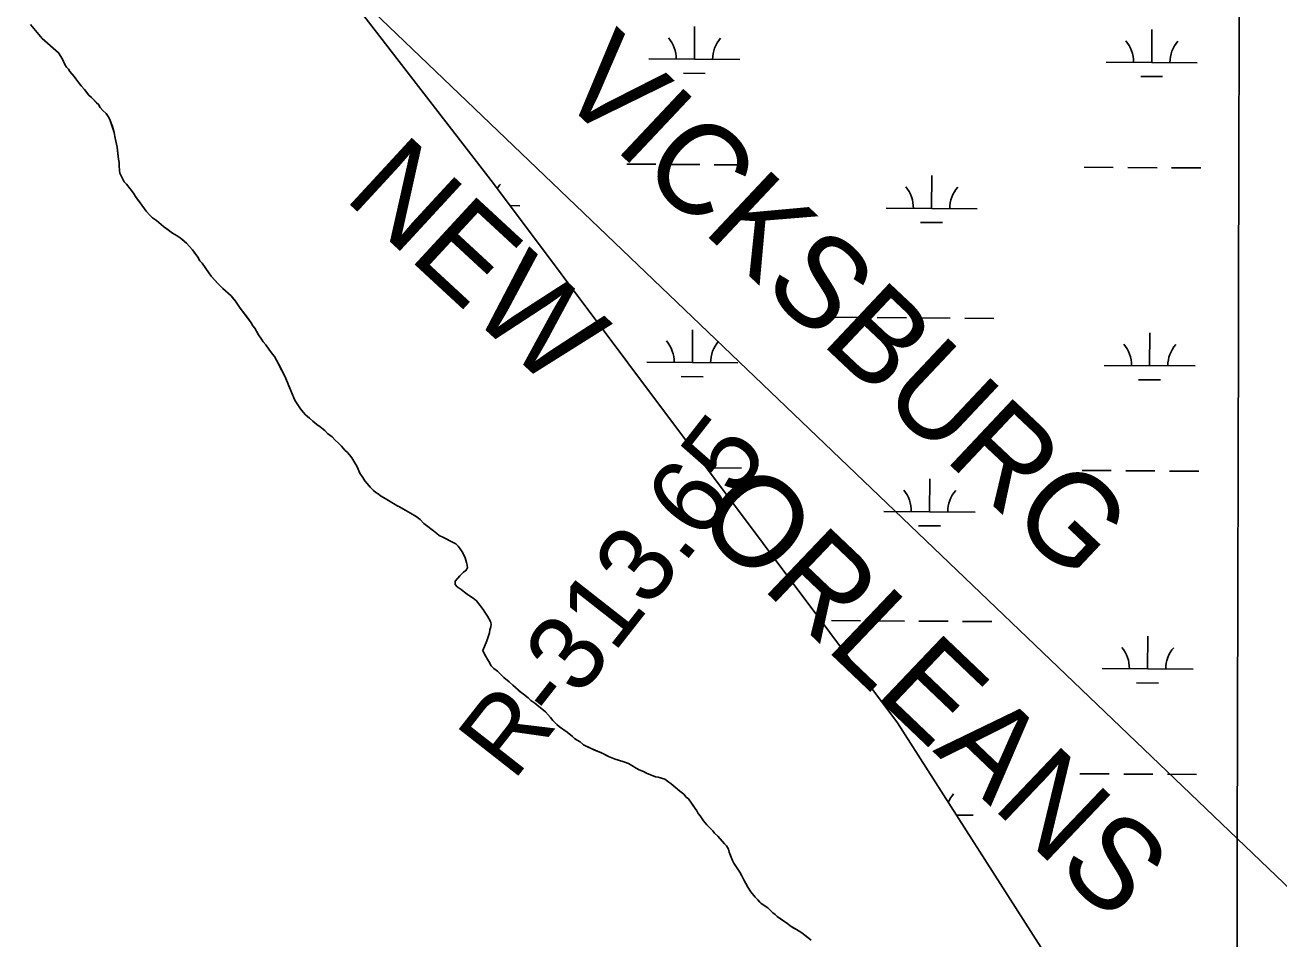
# Model space of a CAD drawing. Extents: x 3172231 to 3210228, y 940198 to 965780.
# Drawn here: x 3196029 to 3197406, y 947239 to 948241 of the extents above; entities that cross this region are included whole.
import ezdxf

# ---------------------------------------------------------------- set-up
doc = ezdxf.new("R2010")
doc.units = 0
for name, color, linetype in [('V-GRID-MAJR', 7, 'Continuous'), ('V-RIVR-RANG-IDEN', 7, 'Continuous'), ('V-SITE-VEGE', 7, 'Continuous'), ('V-TOPO-BNDY', 7, 'Continuous'), ('V-TOPO-GNAM-IDEN', 7, 'Continuous'), ('V-TOPO-SHOR', 7, 'Continuous'), ('V-WETL-SWMP', 7, 'Continuous')]:
    doc.layers.add(name, color=color, linetype=linetype)

msp = doc.modelspace()

# ---------------------------------------------------------------- linework, layer by layer
at = {"layer": 'V-GRID-MAJR'}
msp.add_spline([(3197355.974, 945678.243), (3197370.077, 951738.379), (3197384.187, 957801.599), (3197398.298, 963864.87), (3197398.305, 963867.904)], degree=3, dxfattribs=at)
at = {"layer": 'V-SITE-VEGE'}
for p, q in [((3196035.421, 948241.825), (3196048.367, 948226.26)), ((3196048.367, 948226.26), (3196066.192, 948210.847)), ((3196066.192, 948210.847), (3196070.723, 948203.693)), ((3196070.723, 948203.693), (3196073.135, 948198.035)), ((3196073.135, 948198.035), (3196074.859, 948195.028)), ((3196074.859, 948195.028), (3196077.014, 948192.884)), ((3196077.014, 948192.884), (3196078.736, 948190.31)), ((3196078.736, 948190.31), (3196083.475, 948184.731)), ((3196083.475, 948184.731), (3196085.2, 948182.155)), ((3196085.2, 948182.155), (3196088.645, 948177.862)), ((3196088.645, 948177.862), (3196091.229, 948174.43)), ((3196091.229, 948174.43), (3196094.676, 948170.567)), ((3196094.676, 948170.567), (3196099.415, 948164.13)), ((3196099.415, 948164.13), (3196102.428, 948161.558)), ((3196102.428, 948161.558), (3196110.177, 948153.835)), ((3196110.177, 948153.835), (3196111.904, 948150.83)), ((3196111.904, 948150.83), (3196114.916, 948147.398)), ((3196114.916, 948147.398), (3196118.361, 948143.966)), ((3196118.361, 948143.966), (3196120.516, 948140.959)), ((3196120.516, 948140.959), (3196122.672, 948137.527)), ((3196122.672, 948137.527), (3196127.425, 948123.352)), ((3196127.425, 948123.352), (3196127.864, 948119.056)), ((3196127.864, 948119.056), (3196129.162, 948113.901)), ((3196129.162, 948113.901), (3196130.465, 948107.028)), ((3196130.465, 948107.028), (3196132.21, 948094.136)), ((3196132.21, 948094.136), (3196132.644, 948090.269)), ((3196132.644, 948090.269), (3196132.65, 948086.83)), ((3196132.65, 948086.83), (3196133.088, 948081.674)), ((3196133.088, 948081.674), (3196133.524, 948078.665)), ((3196133.524, 948078.665), (3196138.27, 948069.22)), ((3196138.27, 948069.22), (3196140.852, 948066.645)), ((3196140.852, 948066.645), (3196144.729, 948061.495)), ((3196144.729, 948061.495), (3196148.608, 948056.774)), ((3196148.608, 948056.774), (3196150.762, 948052.909)), ((3196150.762, 948052.909), (3196155.934, 948046.042)), ((3196155.934, 948046.042), (3196162.395, 948037.029)), ((3196162.395, 948037.029), (3196166.272, 948032.739)), ((3196166.272, 948032.739), (3196169.287, 948029.736)), ((3196169.287, 948029.736), (3196173.589, 948026.736)), ((3196173.589, 948026.736), (3196181.337, 948020.303)), ((3196181.337, 948020.303), (3196191.235, 948013.014)), ((3196191.235, 948013.014), (3196196.398, 948010.014)), ((3196196.398, 948010.014), (3196199.843, 948007.872)), ((3196199.843, 948007.872), (3196206.728, 948001.869)), ((3196206.728, 948001.869), (3196213.19, 947994.572)), ((3196213.19, 947994.572), (3196219.221, 947986.419)), ((3196219.221, 947986.419), (3196221.377, 947982.554)), ((3196221.377, 947982.554), (3196223.96, 947979.98)), ((3196223.96, 947979.98), (3196231.286, 947969.251)), ((3196231.286, 947969.251), (3196233.87, 947965.816)), ((3196233.87, 947965.816), (3196241.194, 947957.663)), ((3196241.194, 947957.663), (3196243.776, 947955.089)), ((3196243.776, 947955.089), (3196246.359, 947952.086)), ((3196246.359, 947952.086), (3196255.831, 947943.939)), ((3196255.831, 947943.939), (3196260.568, 947938.359)), ((3196260.568, 947938.359), (3196265.739, 947930.634)), ((3196265.739, 947930.634), (3196277.804, 947914.323)), ((3196277.804, 947914.323), (3196279.528, 947911.319)), ((3196279.528, 947911.319), (3196281.683, 947908.743)), ((3196281.683, 947908.743), (3196283.407, 947905.308)), ((3196283.407, 947905.308), (3196285.564, 947901.445)), ((3196285.564, 947901.445), (3196289.011, 947896.723)), ((3196289.011, 947896.723), (3196290.735, 947893.716)), ((3196290.735, 947893.716), (3196293.75, 947890.284)), ((3196293.75, 947890.284), (3196297.196, 947885.563)), ((3196297.196, 947885.563), (3196301.075, 947879.982)), ((3196301.075, 947879.982), (3196303.23, 947877.41)), ((3196303.23, 947877.41), (3196307.541, 947869.681)), ((3196307.541, 947869.681), (3196313.578, 947858.087)), ((3196313.578, 947858.087), (3196315.737, 947853.363)), ((3196315.737, 947853.363), (3196320.916, 947840.907)), ((3196320.916, 947840.907), (3196324.373, 947832.321)), ((3196324.373, 947832.321), (3196326.098, 947828.885)), ((3196326.098, 947828.885), (3196328.682, 947824.592)), ((3196328.682, 947824.592), (3196331.699, 947820.3)), ((3196331.699, 947820.3), (3196334.716, 947816.437)), ((3196334.716, 947816.437), (3196337.298, 947813.433)), ((3196337.298, 947813.433), (3196341.603, 947810.002)), ((3196341.603, 947810.002), (3196345.478, 947806.572)), ((3196345.478, 947806.572), (3196349.783, 947803.141)), ((3196349.783, 947803.141), (3196353.226, 947800.569)), ((3196353.226, 947800.569), (3196358.391, 947796.281)), ((3196358.391, 947796.281), (3196361.403, 947793.276)), ((3196361.403, 947793.276), (3196366.566, 947789.42)), ((3196366.566, 947789.42), (3196369.583, 947785.985)), ((3196369.583, 947785.985), (3196373.888, 947782.127)), ((3196373.888, 947782.127), (3196376.903, 947779.123)), ((3196376.903, 947779.123), (3196380.349, 947774.832)), ((3196380.349, 947774.832), (3196383.362, 947772.258)), ((3196383.362, 947772.258), (3196385.514, 947769.683)), ((3196385.514, 947769.683), (3196388.097, 947766.251)), ((3196388.097, 947766.251), (3196393.702, 947757.236)), ((3196393.702, 947757.236), (3196396.727, 947749.504)), ((3196396.727, 947749.504), (3196400.174, 947744.784)), ((3196400.174, 947744.784), (3196402.329, 947741.349)), ((3196402.329, 947741.349), (3196404.913, 947738.345)), ((3196404.913, 947738.345), (3196408.36, 947734.052)), ((3196408.36, 947734.052), (3196411.807, 947730.622)), ((3196411.807, 947730.622), (3196414.387, 947728.478)), ((3196414.387, 947728.478), (3196416.97, 947726.763)), ((3196416.97, 947726.763), (3196419.55, 947724.619)), ((3196419.55, 947724.619), (3196422.993, 947722.909)), ((3196422.993, 947722.909), (3196433.749, 947716.478)), ((3196433.749, 947716.478), (3196438.482, 947713.478)), ((3196438.482, 947713.478), (3196438.914, 947713.48)), ((3196438.914, 947713.48), (3196447.516, 947708.768)), ((3196447.516, 947708.768), (3196452.679, 947705.769)), ((3196452.679, 947705.769), (3196458.704, 947701.913)), ((3196458.704, 947701.913), (3196463.009, 947698.911)), ((3196463.009, 947698.911), (3196467.314, 947694.192)), ((3196467.314, 947694.192), (3196469.894, 947692.048)), ((3196469.894, 947692.048), (3196477.642, 947686.475)), ((3196477.642, 947686.475), (3196481.516, 947683.473)), ((3196481.516, 947683.473), (3196484.097, 947681.328)), ((3196484.097, 947681.328), (3196488.83, 947679.188)), ((3196488.83, 947679.188), (3196492.273, 947677.046)), ((3196492.273, 947677.046), (3196495.713, 947675.334)), ((3196495.713, 947675.334), (3196502.166, 947671.908)), ((3196502.166, 947671.908), (3196504.749, 947669.333)), ((3196504.749, 947669.333), (3196506.901, 947666.759)), ((3196506.901, 947666.759), (3196509.92, 947662.036)), ((3196509.92, 947662.036), (3196512.511, 947656.884)), ((3196512.511, 947656.884), (3196513.807, 947651.729)), ((3196513.807, 947651.729), (3196514.674, 947648.722)), ((3196514.674, 947648.722), (3196515.108, 947645.714)), ((3196506.529, 947637.102), (3196501.382, 947631.077)), ((3196510.819, 947640.979), (3196506.529, 947637.102)), ((3196513.396, 947642.701), (3196510.819, 947640.979)), ((3196515.108, 947645.714), (3196513.396, 947642.701)), ((3196501.382, 947631.077), (3196501.388, 947627.638)), ((3196501.388, 947627.638), (3196503.543, 947625.064)), ((3196503.543, 947625.064), (3196508.274, 947622.063)), ((3196508.274, 947622.063), (3196511.718, 947619.061)), ((3196511.718, 947619.061), (3196516.023, 947615.631)), ((3196516.023, 947615.631), (3196521.188, 947612.632)), ((3196521.188, 947612.632), (3196525.059, 947609.63)), ((3196525.059, 947609.63), (3196532.383, 947600.189)), ((3196532.383, 947600.189), (3196534.107, 947597.182)), ((3196534.107, 947597.182), (3196537.124, 947592.892)), ((3196537.124, 947592.892), (3196540.145, 947586.879)), ((3196539.731, 947577.853), (3196539.307, 947574.415)), ((3196540.585, 947580.864), (3196539.731, 947577.853)), ((3196540.145, 947586.879), (3196541.009, 947583.872)), ((3196541.009, 947583.872), (3196540.585, 947580.864)), ((3196536.315, 947565.811), (3196532.037, 947555.061)), ((3196539.307, 947574.415), (3196536.315, 947565.811)), ((3196532.037, 947555.061), (3196533.761, 947551.197)), ((3196533.761, 947551.197), (3196538.504, 947543.037)), ((3196538.504, 947543.037), (3196541.093, 947538.317)), ((3196541.093, 947538.317), (3196544.105, 947535.312)), ((3196544.105, 947535.312), (3196547.98, 947532.312)), ((3196547.98, 947532.312), (3196554.87, 947525.447)), ((3196554.87, 947525.447), (3196560.895, 947520.73)), ((3196560.895, 947520.73), (3196564.77, 947516.87)), ((3196564.77, 947516.87), (3196573.81, 947509.149)), ((3196573.81, 947509.149), (3196576.392, 947507.009)), ((3196576.392, 947507.009), (3196581.557, 947503.148)), ((3196581.557, 947503.148), (3196584.572, 947500.144)), ((3196584.572, 947500.144), (3196588.875, 947497.144)), ((3196588.875, 947497.144), (3196593.178, 947493.713)), ((3196593.178, 947493.713), (3196596.62, 947491.141)), ((3196596.62, 947491.141), (3196600.495, 947487.711)), ((3196600.495, 947487.711), (3196606.094, 947481.704)), ((3196606.094, 947481.704), (3196608.679, 947478.269)), ((3196608.679, 947478.269), (3196612.984, 947473.981)), ((3196612.984, 947473.981), (3196615.998, 947471.406)), ((3196615.998, 947471.406), (3196624.606, 947465.406)), ((3196624.606, 947465.406), (3196630.199, 947460.687)), ((3196630.199, 947460.687), (3196632.354, 947458.543)), ((3196632.354, 947458.543), (3196635.364, 947456.831)), ((3196635.364, 947456.831), (3196638.807, 947454.687)), ((3196638.807, 947454.687), (3196642.252, 947451.684)), ((3196642.252, 947451.684), (3196650.853, 947447.404)), ((3196650.853, 947447.404), (3196662.037, 947442.696)), ((3196662.037, 947442.696), (3196669.781, 947438.841)), ((3196669.781, 947438.841), (3196677.092, 947435.847)), ((3196677.092, 947435.847), (3196685.694, 947433.285)), ((3196685.694, 947433.285), (3196691.713, 947431.147)), ((3196691.713, 947431.147), (3196695.586, 947429.005)), ((3196695.586, 947429.005), (3196700.321, 947426.004)), ((3196700.321, 947426.004), (3196703.329, 947424.29)), ((3196703.329, 947424.29), (3196708.062, 947422.15)), ((3196708.062, 947422.15), (3196711.501, 947420.436)), ((3196711.501, 947420.436), (3196721.395, 947416.588)), ((3196721.395, 947416.588), (3196724.405, 947416.164)), ((3196724.405, 947416.164), (3196731.715, 947414.028)), ((3196731.715, 947414.028), (3196734.727, 947411.885)), ((3196734.727, 947411.885), (3196738.602, 947408.883)), ((3196738.602, 947408.883), (3196748.072, 947400.734)), ((3196748.072, 947400.734), (3196752.375, 947397.306)), ((3196752.375, 947397.306), (3196754.959, 947394.301)), ((3196754.959, 947394.301), (3196757.542, 947392.157)), ((3196757.542, 947392.157), (3196764.868, 947381.856)), ((3196764.868, 947381.856), (3196766.592, 947379.279)), ((3196766.592, 947379.279), (3196768.316, 947376.275)), ((3196768.316, 947376.275), (3196770.471, 947373.7)), ((3196770.471, 947373.7), (3196773.918, 947368.12)), ((3196773.918, 947368.12), (3196777.795, 947363.827)), ((3196777.795, 947363.827), (3196784.254, 947357.392)), ((3196784.254, 947357.392), (3196785.976, 947354.818)), ((3196785.976, 947354.818), (3196789.851, 947351.385)), ((3196789.851, 947351.385), (3196797.173, 947342.804)), ((3196797.173, 947342.804), (3196799.325, 947340.658)), ((3196799.325, 947340.658), (3196801.482, 947337.226)), ((3196801.482, 947337.226), (3196802.348, 947333.787)), ((3196802.348, 947333.787), (3196805.803, 947324.77)), ((3196805.803, 947324.77), (3196807.523, 947321.763)), ((3196807.523, 947321.763), (3196810.974, 947316.182)), ((3196810.974, 947316.182), (3196813.991, 947311.89)), ((3196813.991, 947311.89), (3196816.147, 947308.027)), ((3196816.147, 947308.027), (3196818.306, 947303.305)), ((3196818.306, 947303.305), (3196822.617, 947295.575)), ((3196822.617, 947295.575), (3196826.066, 947290.425)), ((3196826.066, 947290.425), (3196830.803, 947284.416)), ((3196830.803, 947284.416), (3196833.818, 947281.411)), ((3196833.818, 947281.411), (3196835.97, 947278.837)), ((3196835.97, 947278.837), (3196836.832, 947277.979)), ((3196836.832, 947277.979), (3196844.578, 947272.836)), ((3196844.578, 947272.836), (3196850.175, 947267.26)), ((3196850.175, 947267.26), (3196852.757, 947265.546)), ((3196852.757, 947265.546), (3196854.908, 947263.399)), ((3196854.908, 947263.399), (3196866.528, 947255.256)), ((3196866.528, 947255.256), (3196869.113, 947253.11)), ((3196869.113, 947253.11), (3196875.996, 947248.826)), ((3196875.996, 947248.826), (3196882.019, 947245.399)), ((3196882.019, 947245.399), (3196892.349, 947237.252))]:
    msp.add_line(p, q, dxfattribs=at)
at = {"layer": 'V-TOPO-BNDY'}
msp.add_line((3194332.024, 950245.511), (3197716.878, 947007.215), dxfattribs=at)
at = {"layer": 'V-TOPO-SHOR'}
for points in [[(3196070.723, 948203.693), (3196066.192, 948210.847), (3196048.367, 948226.26), (3196035.421, 948241.825)], [(3196169.287, 948029.736), (3196166.272, 948032.739), (3196162.395, 948037.029), (3196155.934, 948046.042), (3196153.347, 948049.477), (3196150.762, 948052.909), (3196148.608, 948056.774), (3196144.729, 948061.495), (3196140.852, 948066.645), (3196138.27, 948069.22), (3196136.543, 948072.654), (3196133.524, 948078.665), (3196133.088, 948081.674), (3196132.65, 948086.83), (3196132.644, 948090.267), (3196132.208, 948094.136), (3196131.335, 948100.151), (3196130.465, 948107.026), (3196129.162, 948113.901), (3196127.864, 948119.056), (3196127.425, 948123.352), (3196125.265, 948129.795), (3196123.968, 948133.66), (3196122.672, 948137.527), (3196120.516, 948140.959), (3196118.361, 948143.966), (3196114.916, 948147.398), (3196111.904, 948150.83), (3196110.177, 948153.835), (3196108.025, 948155.979), (3196102.428, 948161.558), (3196099.415, 948164.13), (3196097.26, 948167.135), (3196094.676, 948170.567), (3196091.229, 948174.43), (3196088.645, 948177.862), (3196085.2, 948182.155), (3196083.475, 948184.731), (3196081.321, 948187.305), (3196078.736, 948190.31), (3196077.014, 948192.884), (3196074.859, 948195.028), (3196073.135, 948198.035), (3196070.723, 948203.693)], [(3196513.807, 947651.729), (3196512.509, 947656.884), (3196509.92, 947662.036), (3196506.904, 947666.759), (3196504.749, 947669.333), (3196502.166, 947671.908), (3196495.713, 947675.334), (3196492.273, 947677.046), (3196488.83, 947679.188), (3196484.097, 947681.328), (3196481.516, 947683.473), (3196477.642, 947686.475), (3196469.896, 947692.048), (3196467.314, 947694.192), (3196463.007, 947698.911), (3196458.704, 947701.913), (3196452.679, 947705.769), (3196447.516, 947708.768), (3196443.645, 947710.91), (3196438.912, 947713.48), (3196438.482, 947713.478), (3196433.749, 947716.478), (3196422.993, 947722.907), (3196419.55, 947724.619), (3196416.97, 947726.763), (3196414.387, 947728.478), (3196411.805, 947730.622), (3196408.36, 947734.052), (3196404.913, 947738.345), (3196402.329, 947741.349), (3196400.174, 947744.784), (3196396.727, 947749.504), (3196395.001, 947753.799), (3196393.704, 947757.236), (3196390.256, 947762.816), (3196388.099, 947766.251), (3196385.514, 947769.683), (3196383.362, 947772.258), (3196380.349, 947774.832), (3196376.903, 947779.123), (3196373.888, 947782.127), (3196369.583, 947785.985), (3196366.568, 947789.42), (3196361.403, 947793.276), (3196358.391, 947796.281), (3196353.226, 947800.569), (3196349.783, 947803.141), (3196345.478, 947806.572), (3196341.603, 947810.002), (3196337.298, 947813.433), (3196334.716, 947816.437), (3196331.699, 947820.3), (3196328.682, 947824.592), (3196326.098, 947828.885), (3196324.371, 947832.319), (3196320.916, 947840.909), (3196318.76, 947846.063), (3196317.464, 947849.07), (3196315.737, 947853.363), (3196313.578, 947858.087), (3196309.265, 947866.244), (3196307.541, 947869.681), (3196305.384, 947873.544), (3196303.23, 947877.408), (3196301.075, 947879.982), (3196298.921, 947882.989), (3196297.196, 947885.563), (3196293.75, 947890.284), (3196290.735, 947893.716), (3196289.011, 947896.723), (3196285.564, 947901.443), (3196283.407, 947905.308), (3196281.683, 947908.743), (3196279.528, 947911.319), (3196277.804, 947914.323), (3196273.065, 947920.76), (3196265.739, 947930.634), (3196260.568, 947938.359), (3196257.983, 947941.363), (3196255.831, 947943.937), (3196246.359, 947952.086), (3196243.776, 947955.091), (3196241.194, 947957.663), (3196238.177, 947961.098), (3196233.87, 947965.816), (3196231.286, 947969.251), (3196223.96, 947979.98), (3196221.377, 947982.554), (3196219.221, 947986.419), (3196217.066, 947989.423), (3196213.19, 947994.574), (3196206.728, 948001.869), (3196203.285, 948004.872), (3196199.841, 948007.874), (3196196.398, 948010.014), (3196191.235, 948013.014), (3196186.502, 948016.445), (3196181.337, 948020.303), (3196178.755, 948022.447), (3196173.589, 948026.736), (3196169.287, 948029.736)], [(3196816.147, 947308.027), (3196813.991, 947311.892), (3196810.974, 947316.182), (3196807.525, 947321.763), (3196805.803, 947324.77), (3196802.348, 947333.787), (3196801.482, 947337.226), (3196799.325, 947340.658), (3196797.173, 947342.804), (3196789.851, 947351.385), (3196785.976, 947354.818), (3196784.254, 947357.392), (3196780.807, 947360.825), (3196777.795, 947363.827), (3196773.918, 947368.12), (3196770.471, 947373.7), (3196768.316, 947376.275), (3196766.592, 947379.279), (3196764.868, 947381.856), (3196762.713, 947384.86), (3196757.542, 947392.157), (3196754.959, 947394.301), (3196752.375, 947397.306), (3196748.072, 947400.734), (3196745.057, 947403.308), (3196738.602, 947408.883), (3196734.727, 947411.885), (3196731.715, 947414.028), (3196724.405, 947416.164), (3196721.395, 947416.588), (3196711.503, 947420.438), (3196708.062, 947422.15), (3196703.329, 947424.29), (3196700.319, 947426.004), (3196695.586, 947429.005), (3196691.713, 947431.147), (3196685.694, 947433.285), (3196677.092, 947435.847), (3196669.781, 947438.841), (3196666.338, 947440.555), (3196662.037, 947442.696), (3196659.027, 947443.98), (3196653.866, 947446.12), (3196650.853, 947447.404), (3196647.413, 947449.116), (3196642.252, 947451.684), (3196638.807, 947454.687), (3196635.364, 947456.831), (3196632.354, 947458.543), (3196631.061, 947459.829), (3196630.199, 947460.687), (3196624.604, 947465.406), (3196615.998, 947471.406), (3196612.984, 947473.981), (3196608.679, 947478.269), (3196606.094, 947481.704), (3196600.495, 947487.711), (3196596.62, 947491.141), (3196593.178, 947493.713), (3196588.875, 947497.144), (3196584.572, 947500.144), (3196581.557, 947503.148), (3196576.392, 947507.007), (3196573.81, 947509.149), (3196570.797, 947511.723), (3196564.77, 947516.87), (3196560.895, 947520.73), (3196554.87, 947525.447), (3196552.285, 947528.021), (3196547.98, 947532.312), (3196544.105, 947535.312), (3196541.093, 947538.317), (3196538.504, 947543.037), (3196533.761, 947551.197), (3196532.037, 947555.061), (3196533.747, 947559.362), (3196536.315, 947565.813), (3196539.307, 947574.415), (3196539.731, 947577.853), (3196540.585, 947580.864), (3196541.009, 947583.872), (3196540.145, 947586.879), (3196537.124, 947592.892), (3196534.107, 947597.182), (3196532.383, 947600.189), (3196527.644, 947606.198), (3196525.059, 947609.63), (3196521.186, 947612.632), (3196516.023, 947615.631), (3196511.718, 947619.061), (3196508.276, 947622.063), (3196503.543, 947625.064), (3196501.388, 947627.638), (3196501.382, 947631.077), (3196504.384, 947634.519), (3196506.529, 947637.102), (3196510.819, 947640.979), (3196513.396, 947642.701), (3196515.108, 947645.714), (3196514.674, 947648.722), (3196513.807, 947651.729)], [(3196892.349, 947237.252), (3196888.475, 947240.253), (3196882.019, 947245.399), (3196875.996, 947248.826), (3196872.553, 947250.97), (3196869.113, 947253.11), (3196866.528, 947255.256), (3196862.225, 947258.257), (3196854.91, 947263.399), (3196852.757, 947265.546), (3196850.175, 947267.26), (3196847.16, 947270.262), (3196844.578, 947272.836), (3196840.705, 947275.409), (3196836.832, 947277.979), (3196835.97, 947278.837), (3196835.97, 947278.837), (3196833.818, 947281.411), (3196830.803, 947284.416), (3196826.066, 947290.425), (3196822.617, 947295.575), (3196818.306, 947303.303), (3196816.147, 947308.027)]]:
    msp.add_lwpolyline(points, dxfattribs=at)
at = {"layer": 'V-WETL-SWMP'}
for p, q in [((3196543.471, 948067.222), (3195915.087, 948880.76)), ((3196764.079, 948203.582), (3196764.324, 948239.581)), ((3197265.975, 948200.165), (3197266.22, 948236.164)), ((3196714.08, 948203.922), (3196814.078, 948203.241)), ((3197215.976, 948200.505), (3197315.974, 948199.825)), ((3196751.974, 948188.233), (3196775.974, 948188.069)), ((3197253.871, 948184.816), (3197277.87, 948184.653)), ((3196689.887, 948088.652), (3196721.886, 948088.434)), ((3196737.886, 948088.325), (3196769.885, 948088.107)), ((3196785.885, 948087.998), (3196817.884, 948087.781)), ((3197024.407, 948039.944), (3197024.652, 948075.943)), ((3197191.783, 948085.235), (3197223.783, 948085.018)), ((3197239.782, 948084.909), (3197271.781, 948084.691)), ((3197287.781, 948084.582), (3197319.78, 948084.364)), ((3196987.037, 947475.557), (3196543.471, 948067.222)), ((3196561.559, 948043.094), (3196572.51, 948043.02)), ((3196974.408, 948040.284), (3197074.406, 948039.603)), ((3197012.302, 948024.595), (3197036.302, 948024.431)), ((3196916.748, 947920.603), (3196948.748, 947920.385)), ((3196964.747, 947920.276), (3196996.746, 947920.058)), ((3197012.746, 947919.949), (3197044.745, 947919.732)), ((3197060.745, 947919.623), (3197092.744, 947919.405)), ((3196761.814, 947870.914), (3196762.059, 947906.913)), ((3197263.711, 947867.498), (3197263.956, 947903.497)), ((3196711.816, 947871.255), (3196811.813, 947870.574)), ((3197213.712, 947867.838), (3197313.71, 947867.157)), ((3196749.71, 947855.565), (3196773.709, 947855.402)), ((3197251.606, 947852.149), (3197275.606, 947851.986)), ((3196783.62, 947755.331), (3196815.619, 947755.113)), ((3197022.143, 947707.276), (3197022.388, 947743.276)), ((3197189.519, 947752.568), (3197221.518, 947752.35)), ((3197237.518, 947752.241), (3197269.517, 947752.024)), ((3197285.517, 947751.915), (3197317.516, 947751.697)), ((3196972.144, 947707.617), (3197072.141, 947706.936)), ((3197010.038, 947691.928), (3197034.037, 947691.764)), ((3196914.484, 947587.936), (3196946.483, 947587.718)), ((3196962.483, 947587.609), (3196994.482, 947587.391)), ((3197010.482, 947587.282), (3197042.481, 947587.064)), ((3197058.48, 947586.955), (3197090.48, 947586.738)), ((3197261.446, 947534.831), (3197261.691, 947570.83)), ((3197211.447, 947535.171), (3197311.445, 947534.49)), ((3197249.342, 947519.482), (3197273.341, 947519.318)), ((3197578.458, 946551.082), (3196987.037, 947475.557)), ((3197187.254, 947419.901), (3197219.254, 947419.683)), ((3197235.253, 947419.574), (3197267.252, 947419.356)), ((3197283.252, 947419.247), (3197315.251, 947419.03)), ((3197051.756, 947374.392), (3197069.877, 947374.269))]:
    msp.add_line(p, q, dxfattribs=at)
for centre, start, end in [((3196708.841, 948204.432), 358.838165, 40.381824), ((3196819.324, 948203.68), 138.838162, 180.381821), ((3197210.737, 948201.016), 358.838165, 40.381824), ((3197321.22, 948200.264), 138.838162, 180.381821), ((3196577.756, 948043.459), 138.838162, 148.8134), ((3196969.169, 948040.795), 358.838165, 40.381824), ((3197079.652, 948040.043), 138.838162, 180.381821), ((3196706.576, 947871.765), 358.838165, 40.381824), ((3196817.059, 947871.013), 138.838162, 180.381821), ((3197208.472, 947868.349), 358.838165, 40.381824), ((3197318.956, 947867.597), 138.838162, 180.381821), ((3196966.904, 947708.127), 358.838165, 40.381824), ((3197077.387, 947707.375), 138.838162, 180.381821), ((3197206.208, 947535.681), 358.838165, 40.381824), ((3197316.691, 947534.929), 138.838162, 180.381821), ((3197075.123, 947374.708), 138.838162, 156.892275)]:
    msp.add_arc(centre, 35.246, start, end, dxfattribs=at)

# ---------------------------------------------------------------- texts
at = {"layer": 'V-RIVR-RANG-IDEN'}
msp.add_text('R-313.65', height=82.9998, rotation=51.919007, dxfattribs=at).set_placement((3196565.213, 947410.536))
at = {"layer": 'V-TOPO-GNAM-IDEN'}
for s, rotation, p in [('VICKSBURG', 316.716894, (3196609.482, 948168.021)), ('NEW ', 317.28439, (3196377.975, 948051.441)), (' ORLEANS', 316.37481, (3196734.427, 947721.819))]:
    msp.add_text(s, height=99.9998, rotation=rotation, dxfattribs=at).set_placement(p)

doc.saveas('drawing.dxf')
